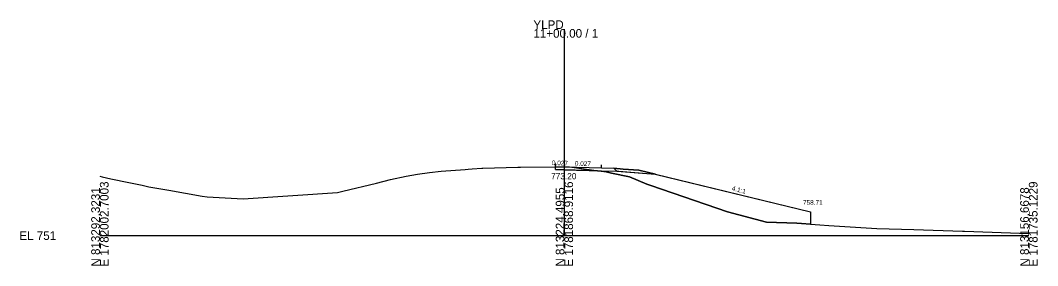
# Model space of a CAD drawing. Extents: x -26 to 353, y -10 to 9080.
# Drawn here: x -25.7 to 302.8, y 990.3 to 1069.5 of the extents above; entities that cross this region are included whole.
import ezdxf

# ---------------------------------------------------------------- set-up
doc = ezdxf.new("R2010")
doc.units = 0
for name, color, linetype in [('Exist Cross Section Cell', 7, 'Continuous'), ('Exist XS Center Line Elevation Label', 7, 'Continuous'), ('Exist XS Ground Line', 7, 'Continuous'), ('Prop XS Ditch Standard Text', 7, 'Continuous'), ('Prop XS Dump Level', 7, 'Continuous'), ('Prop XS Earthwork Shape', 7, 'Continuous'), ('Prop XS EOT Tick Mark', 7, 'Continuous'), ('Prop XS Finish Grade', 7, 'Continuous'), ('Prop XS Finish Grade Earthwork', 7, 'Continuous'), ('Prop XS Finish Grade Paved Shoulder', 7, 'Continuous'), ('Prop XS Finish Grade Pavement', 7, 'Continuous'), ('Prop XS Pvmt Edge Slope', 7, 'Continuous'), ('Prop XS SE Text', 7, 'Continuous'), ('Prop XS Side Slope Text', 7, 'Continuous'), ('Prop XS Subgrade Earthwork', 7, 'Continuous'), ('Scratch_Level_3', 7, 'Continuous')]:
    doc.layers.add(name, color=color, linetype=linetype)

msp = doc.modelspace()

# ---------------------------------------------------------------- linework, layer by layer
at = {"layer": 'Exist Cross Section Cell'}
for p, q in [((150, 1000), (150, 1066.71)), ((0, 1000), (150, 1000)), ((150, 1000), (300, 1000))]:
    msp.add_line(p, q, dxfattribs=at)
at = {"layer": 'Exist XS Ground Line'}
for p, q in [((120.21, 1021.54), (123.35, 1021.77)), ((123.35, 1021.77), (123.68, 1021.8)), ((123.68, 1021.8), (134.92, 1022.09)), ((134.92, 1022.09), (135.38, 1022.1)), ((135.38, 1022.1), (135.78, 1022.11)), ((135.78, 1022.11), (147.19, 1022.24)), ((147.19, 1022.24), (150, 1022.2)), ((150, 1022.2), (151.66, 1022.18)), ((151.66, 1022.18), (163.49, 1020.59)), ((0, 1019.21), (0.7, 1019.03)), ((0.7, 1019.03), (3.54, 1018.31)), ((93.85, 1018.08), (98.9, 1019.24)), ((98.9, 1019.24), (102.53, 1019.82)), ((102.53, 1019.82), (106.43, 1020.36)), ((106.43, 1020.36), (110.16, 1020.81)), ((110.16, 1020.81), (117.91, 1021.36)), ((117.91, 1021.36), (118.96, 1021.43)), ((118.96, 1021.43), (120.21, 1021.54)), ((163.49, 1020.59), (165.24, 1020.2)), ((165.24, 1020.2), (171.05, 1018.99)), ((171.05, 1018.99), (176.58, 1016.67)), ((3.54, 1018.31), (9.37, 1017.12)), ((9.37, 1017.12), (13.68, 1016.28)), ((13.68, 1016.28), (15.84, 1015.78)), ((15.84, 1015.78), (22.29, 1014.68)), ((78.47, 1014.33), (89.36, 1016.99)), ((89.36, 1016.99), (93.85, 1018.08)), ((176.58, 1016.67), (177.6, 1016.3)), ((177.6, 1016.3), (177.92, 1016.19)), ((177.92, 1016.19), (202.69, 1007.64)), ((22.29, 1014.68), (33, 1012.76)), ((33, 1012.76), (34.65, 1012.54)), ((34.65, 1012.54), (46.29, 1011.86)), ((46.29, 1011.86), (76.77, 1013.97)), ((76.77, 1013.97), (78.47, 1014.33)), ((202.69, 1007.64), (215.23, 1004.38)), ((215.23, 1004.38), (225.03, 1004.03)), ((225.03, 1004.03), (232.52, 1003.51)), ((232.52, 1003.51), (235.43, 1003.3)), ((235.43, 1003.3), (250.89, 1002.27)), ((250.89, 1002.27), (262.86, 1001.97)), ((262.86, 1001.97), (278.55, 1001.48)), ((278.55, 1001.48), (278.85, 1001.49)), ((278.85, 1001.49), (279.19, 1001.48)), ((279.19, 1001.48), (300, 1000.74))]:
    msp.add_line(p, q, dxfattribs=at)
at = {"layer": 'Prop XS Dump Level'}
for p, q in [((147.16, 1022.24), (150, 1022.17)), ((150, 1022.17), (162, 1021.85))]:
    msp.add_line(p, q, dxfattribs=at)
at = {"layer": 'Prop XS Earthwork Shape'}
for points in [[(147.16, 1022.24), (147.19, 1022.24), (150, 1022.2), (151.66, 1022.18), (160.68, 1020.96), (149.98, 1021.25), (147.16, 1021.33)], [(167.6, 1020.78), (179.36, 1019.84), (229.5, 1007.71), (229.5, 1003.72), (225.03, 1004.03), (215.23, 1004.38), (202.69, 1007.64), (177.92, 1016.19), (177.6, 1016.3), (176.58, 1016.67), (171.05, 1018.99), (165.24, 1020.2), (163.49, 1020.59), (160.68, 1020.96), (161.98, 1020.93)]]:
    msp.add_lwpolyline(points, close=True, dxfattribs=at)
at = {"layer": 'Prop XS EOT Tick Mark'}
for p, q in [((147.16, 1022.24), (147.16, 1023.24)), ((162, 1021.85), (162, 1022.85))]:
    msp.add_line(p, q, dxfattribs=at)
at = {"layer": 'Prop XS Finish Grade'}
for p, q in [((166, 1021.74), (169, 1021.5)), ((169, 1021.5), (174, 1021.1)), ((174, 1021.1), (179.38, 1019.8))]:
    msp.add_line(p, q, dxfattribs=at)
at = {"layer": 'Prop XS Finish Grade Earthwork'}
for p, q in [((179.38, 1019.8), (229.5, 1007.71)), ((229.5, 1007.71), (229.5, 1003.72))]:
    msp.add_line(p, q, dxfattribs=at)
at = {"layer": 'Prop XS Finish Grade Paved Shoulder'}
msp.add_line((162, 1021.85), (166, 1021.74), dxfattribs=at)
at = {"layer": 'Prop XS Finish Grade Pavement'}
for p, q in [((147.16, 1022.24), (150, 1022.17)), ((150, 1022.17), (162, 1021.85))]:
    msp.add_line(p, q, dxfattribs=at)
at = {"layer": 'Prop XS Pvmt Edge Slope'}
msp.add_line((166, 1021.74), (166.94, 1020.8), dxfattribs=at)
at = {"layer": 'Prop XS Subgrade Earthwork'}
for p, q in [((147.16, 1021.33), (147.16, 1022.24)), ((147.16, 1021.33), (149.98, 1021.25)), ((149.98, 1021.25), (161.98, 1020.93)), ((161.98, 1020.93), (166.94, 1020.8)), ((166.94, 1020.8), (179.38, 1019.8))]:
    msp.add_line(p, q, dxfattribs=at)
at = {"layer": 'Scratch_Level_3'}
for p, q in [((169, 1021.5), (166, 1021.74)), ((166, 1021.74), (166.94, 1020.8)), ((166.94, 1020.8), (179.38, 1019.8)), ((174, 1021.1), (169, 1021.5)), ((179.38, 1019.8), (174, 1021.1))]:
    msp.add_line(p, q, dxfattribs=at)

# ---------------------------------------------------------------- texts
at = {"layer": 'Exist Cross Section Cell'}
for s, p in [('YLPD', (140, 1066.71)), ('11+00.00 / 1', (140, 1063.91)), ('EL 751', (-26, 998.6))]:
    msp.add_text(s, height=2.8, dxfattribs=at).set_placement(p)
for s, p in [('N 813292.3231', (0, 990)), ('E 1782002.7003', (2.8, 990)), ('N 813224.4955', (150, 990)), ('E 1781868.9116', (152.8, 990)), ('N 813156.6678', (300, 990)), ('E 1781735.1229', (302.8, 990))]:
    msp.add_text(s, height=2.8, rotation=90, dxfattribs=at).set_placement(p)
at = {"layer": 'Exist XS Center Line Elevation Label'}
msp.add_text('773.20', height=2, dxfattribs=at).set_placement((145.71, 1018.2))
at = {"layer": 'Prop XS Ditch Standard Text'}
msp.add_text('758.71', height=1.5, dxfattribs=at).set_placement((227.07, 1009.97))
at = {"layer": 'Prop XS Dump Level'}
msp.add_text('Case4', height=0.04, dxfattribs=at).set_placement((174, 1021.1))
at = {"layer": 'Prop XS SE Text'}
for rotation, p in [(358.4355, (145.95, 1022.78)), (358.474, (153.37, 1022.58))]:
    msp.add_text('0.027', height=1.5, rotation=rotation, dxfattribs=at).set_placement(p)
at = {"layer": 'Prop XS Side Slope Text'}
msp.add_text('4.1:1', height=1.5, rotation=345.9638, dxfattribs=at).set_placement((203.96, 1014.62))

doc.saveas('drawing.dxf')
